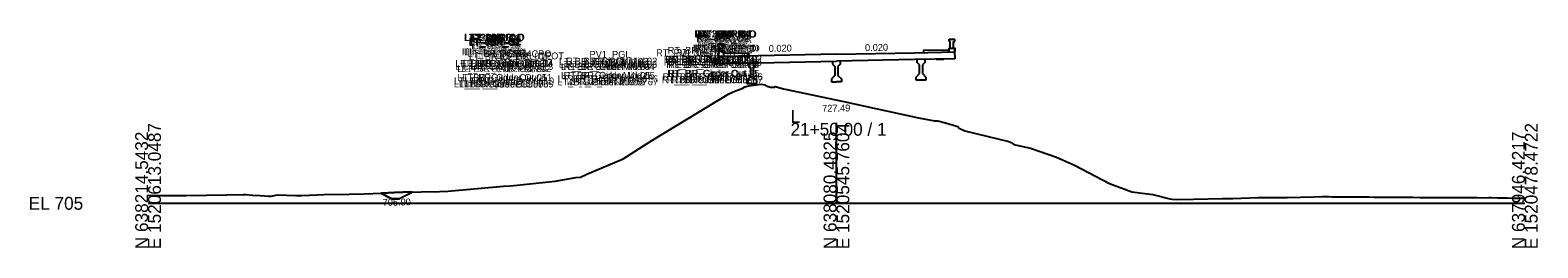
# Model space of a CAD drawing. Extents: x -26 to 3903, y -10 to 9531.
# Drawn here: x 974.3 to 1302.8, y 1490.3 to 1537.7 of the extents above; entities that cross this region are included whole.
import ezdxf

# ---------------------------------------------------------------- set-up
doc = ezdxf.new("R2010")
doc.units = 0
for name, color, linetype in [('Default', 7, 'Continuous'), ('Exist Cross Section Cell', 7, 'Continuous'), ('Exist XS Center Line Elevation Label', 7, 'Continuous'), ('Exist XS Ground Line', 7, 'Continuous'), ('Prop CMT Conc Surface', 7, 'Continuous'), ('Prop XS Conc Monolithic Island', 7, 'Continuous'), ('Prop XS DDE', 7, 'Continuous'), ('Prop XS DDE Earthwork Shape', 7, 'Continuous'), ('Prop XS DDE Elevations', 7, 'Continuous'), ('Prop XS Finish Grade', 7, 'Continuous'), ('Prop XS SE Text', 7, 'Continuous')]:
    doc.layers.add(name, color=color, linetype=linetype)

msp = doc.modelspace()

# ---------------------------------------------------------------- linework, layer by layer
at = {"layer": 'Exist Cross Section Cell'}
for p, q in [((1150, 1500), (1150, 1517.51)), ((1000, 1500), (1150, 1500)), ((1150, 1500), (1300, 1500))]:
    msp.add_line(p, q, dxfattribs=at)
at = {"layer": 'Exist XS Ground Line'}
msp.add_lwpolyline([(1000, 1501.78), (1001.17, 1501.73), (1008.31, 1501.73), (1017.15, 1501.81), (1020.77, 1501.91), (1021.28, 1501.91), (1022.78, 1501.76), (1024.46, 1501.67), (1026.29, 1501.53), (1026.84, 1501.56), (1028.21, 1501.85), (1032.1, 1501.68), (1033.11, 1501.73), (1033.51, 1501.73), (1038.36, 1501.92), (1043.83, 1501.99), (1047.1, 1502.05), (1050.91, 1502.2), (1053.72, 1502.33), (1055.55, 1502.41), (1063.49, 1502.58), (1065.31, 1502.67), (1077.43, 1503.73), (1078.88, 1503.82), (1080.46, 1503.95), (1084.55, 1504.36), (1088.7, 1504.81), (1093.24, 1505.59), (1094.2, 1505.71), (1095.62, 1506.33), (1103.56, 1509.7), (1107.94, 1512.5), (1110.51, 1514.08), (1126.52, 1523.8), (1128.02, 1524.46), (1129.44, 1524.99), (1130.03, 1525.35), (1130.87, 1525.58), (1133.57, 1525.91), (1134.43, 1525.82), (1134.67, 1525.56), (1135.15, 1525.44), (1135.65, 1525.32), (1135.79, 1525.28), (1136.04, 1525.28), (1136.42, 1525.29), (1136.56, 1525.3), (1136.64, 1525.46), (1138.46, 1524.94), (1139.2, 1524.79), (1152.3, 1522.01), (1158.84, 1520.59), (1167.88, 1518.61), (1171.38, 1517.99), (1172.13, 1517.97), (1173.79, 1517.55), (1176.46, 1516.7), (1176.72, 1516.35), (1177.97, 1515.81), (1187.57, 1513.45), (1188.09, 1513.22), (1188.69, 1512.78), (1192.31, 1512.04), (1197.97, 1510.07), (1201.88, 1508.32), (1209.49, 1504.3), (1214.39, 1502.5), (1218.97, 1501.93), (1222.63, 1501), (1223.14, 1500.9), (1224.13, 1500.84), (1227.83, 1500.92), (1234.12, 1501.02), (1236.36, 1501.08), (1241.89, 1501.28), (1242.48, 1501.29), (1242.88, 1501.29), (1248.18, 1501.28), (1254.05, 1501.41), (1255.67, 1501.45), (1256.77, 1501.47), (1257.26, 1501.46), (1258, 1501.43), (1258.31, 1501.43), (1258.65, 1501.42), (1258.75, 1501.42), (1260.37, 1501.41), (1261.61, 1501.4), (1262.1, 1501.4), (1262.84, 1501.39), (1263.95, 1501.39), (1264.13, 1501.4), (1264.27, 1501.39), (1264.36, 1501.39), (1266.02, 1501.38), (1267.19, 1501.36), (1267.72, 1501.36), (1268.43, 1501.35), (1270.01, 1501.34), (1271.62, 1501.33), (1272.8, 1501.32), (1273.2, 1501.32), (1273.99, 1501.31), (1275.6, 1501.3), (1277.21, 1501.29), (1278.39, 1501.29), (1278.78, 1501.29), (1279.57, 1501.28), (1281.2, 1501.27), (1282.82, 1501.27), (1283.99, 1501.26), (1285.13, 1501.26), (1286.78, 1501.25), (1288.1, 1501.24), (1289.59, 1501.23), (1290.67, 1501.22), (1292.19, 1501.23), (1292.77, 1501.23), (1294.06, 1501.2), (1295.08, 1501.19), (1295.65, 1501.18), (1296.23, 1501.16), (1297.4, 1501.14), (1297.98, 1501.13), (1299.26, 1501.1), (1300, 1501.09)], dxfattribs=at)
at = {"layer": 'Prop XS Conc Monolithic Island'}
for p, q in [((1124.22, 1534.19), (1124.22, 1534.69)), ((1124.22, 1534.69), (1125.47, 1534.69)), ((1125.47, 1534.19), (1125.47, 1534.69)), ((1174.53, 1535.22), (1174.53, 1535.72)), ((1174.53, 1535.72), (1175.78, 1535.72)), ((1174.78, 1535.22), (1174.53, 1535.22)), ((1174.78, 1533.72), (1174.78, 1535.22)), ((1175.53, 1533.72), (1175.53, 1535.22)), ((1175.53, 1535.22), (1175.78, 1535.22)), ((1175.78, 1535.22), (1175.78, 1535.72)), ((1124.47, 1534.19), (1124.22, 1534.19)), ((1124.22, 1531.93), (1124.22, 1532.69)), ((1124.22, 1532.69), (1124.47, 1532.69)), ((1124.47, 1532.69), (1124.47, 1534.19)), ((1125.22, 1532.69), (1125.22, 1534.19)), ((1125.22, 1534.19), (1125.47, 1534.19)), ((1125.47, 1532.69), (1125.22, 1532.69)), ((1125.47, 1531.93), (1125.47, 1532.69)), ((1174.53, 1532.96), (1174.53, 1533.72)), ((1174.53, 1533.72), (1174.78, 1533.72)), ((1175.78, 1533.72), (1175.53, 1533.72)), ((1175.78, 1532.96), (1175.78, 1533.72))]:
    msp.add_line(p, q, dxfattribs=at)
for points in [[(1150, 1532.44), (1133, 1532.1), (1124.22, 1531.93)], [(1124.22, 1531.93), (1124.25, 1530.43)], [(1126.29, 1531.97), (1131, 1532.06)], [(1150, 1532.44), (1167, 1532.78), (1175.78, 1532.96)], [(1175.78, 1531.46), (1167, 1531.28), (1150, 1530.94)], [(1167.59, 1530.64), (1167.59, 1531.29)], [(1169.26, 1531.33), (1169.26, 1530.64)], [(1171.75, 1531.38), (1172.58, 1531.39), (1173.42, 1531.41)], [(1175.75, 1532.99), (1175.78, 1531.46)], [(1124.25, 1530.43), (1133, 1530.6), (1150, 1530.94)], [(1128.25, 1530.51), (1127.42, 1530.49), (1126.58, 1530.47)], [(1130.74, 1530.56), (1130.74, 1529.91)], [(1130.74, 1529.91), (1131.24, 1529.41)], [(1131.24, 1529.41), (1131.24, 1527.49)], [(1131.91, 1529.41), (1132.41, 1529.91)], [(1131.91, 1527.49), (1131.91, 1529.41)], [(1132.41, 1529.91), (1132.41, 1530.59)], [(1149.67, 1527.86), (1148.92, 1527.11)], [(1149.17, 1530.93), (1149.17, 1530.28)], [(1149.17, 1530.28), (1149.67, 1529.78)], [(1149.67, 1529.78), (1149.67, 1527.86)], [(1150.83, 1530.28), (1150.33, 1529.78)], [(1150.33, 1529.78), (1150.33, 1527.86)], [(1150.33, 1527.86), (1151.08, 1527.11)], [(1150.83, 1530.96), (1150.83, 1530.28)], [(1167.34, 1527.48), (1168.09, 1528.23)], [(1168.09, 1530.14), (1167.59, 1530.64)], [(1168.09, 1528.23), (1168.09, 1530.14)], [(1169.26, 1530.64), (1168.76, 1530.14)], [(1168.76, 1530.14), (1168.76, 1528.23)], [(1168.76, 1528.23), (1169.51, 1527.48)], [(1131.24, 1527.49), (1130.49, 1526.74)], [(1130.49, 1526.74), (1130.49, 1526.07)], [(1130.49, 1526.07), (1131.58, 1526.07), (1132.66, 1526.07)], [(1132.66, 1526.74), (1131.91, 1527.49)], [(1132.66, 1526.07), (1132.66, 1526.74)], [(1148.92, 1527.11), (1148.92, 1526.44)], [(1148.92, 1526.44), (1150, 1526.44)], [(1151.08, 1526.44), (1150, 1526.44)], [(1151.08, 1527.11), (1151.08, 1526.44)], [(1167.34, 1526.81), (1167.34, 1527.48)], [(1169.51, 1526.81), (1168.42, 1526.81), (1167.34, 1526.81)], [(1169.51, 1527.48), (1169.51, 1526.81)]]:
    msp.add_lwpolyline(points, dxfattribs=at)
at = {"layer": 'Prop XS DDE'}
for p, q in [((1053.09, 1501), (1050.7, 1502.19)), ((1054.65, 1501), (1057.56, 1502.45)), ((1054.65, 1501), (1053.09, 1501))]:
    msp.add_line(p, q, dxfattribs=at)
at = {"layer": 'Prop XS DDE Earthwork Shape'}
for p, q in [((1050.7, 1502.19), (1053.09, 1501)), ((1054.65, 1501), (1057.56, 1502.45)), ((1057.56, 1502.45), (1055.55, 1502.41)), ((1053.09, 1501), (1054.65, 1501))]:
    msp.add_line(p, q, dxfattribs=at)
msp.add_lwpolyline([(1055.55, 1502.41), (1053.72, 1502.33), (1050.91, 1502.2), (1050.7, 1502.19)], dxfattribs=at)
at = {"layer": 'Prop XS Finish Grade'}
for p, q in [((1130.93, 1532.06), (1130.93, 1532.62)), ((1169.07, 1532.82), (1169.07, 1533.32))]:
    msp.add_line(p, q, dxfattribs=at)
for points in [[(1130.93, 1532.06), (1130.93, 1532.62), (1125.43, 1532.67), (1125.43, 1533.02), (1124.22, 1533.02), (1124.22, 1531.93)], [(1169.07, 1532.82), (1169.07, 1533.32), (1174.57, 1533.43), (1174.57, 1533.78), (1175.78, 1533.78), (1175.78, 1532.96)]]:
    msp.add_lwpolyline(points, dxfattribs=at)

# ---------------------------------------------------------------- texts
at = {"layer": 'Default'}
msp.add_text('-', height=0.0001, dxfattribs=at).set_placement((1000, 1500))
at = {"layer": 'Exist Cross Section Cell'}
for s, p in [('L', (1140, 1517.51)), ('21+50.00 / 1', (1140, 1514.71)), ('EL 705', (974, 1498.6))]:
    msp.add_text(s, height=2.8, dxfattribs=at).set_placement(p)
for s, p in [('N 638214.5432', (1000, 1490)), ('E 1520613.0487', (1002.8, 1490)), ('N 638080.4825', (1150, 1490)), ('E 1520545.7604', (1152.8, 1490)), ('N 637946.4217', (1300, 1490)), ('E 1520478.4722', (1302.8, 1490))]:
    msp.add_text(s, height=2.8, rotation=90, dxfattribs=at).set_placement(p)
at = {"layer": 'Exist XS Center Line Elevation Label'}
msp.add_text('727.49', height=1.5, rotation=0.8401, dxfattribs=at).set_placement((1146.9, 1519.92))
at = {"layer": 'Prop CMT Conc Surface'}
for s, p in [('RT_2BMRP_O', (1119.01, 1536.17)), ('RT_3BMRP_O', (1119.15, 1536.17)), ('RT_5BMRP_O', (1119.24, 1536.09)), ('RT_3BR_O1', (1119.74, 1536.11)), ('RT_2BR_O1', (1119.97, 1536.17)), ('RT_1BR_O1', (1120.23, 1536.17)), ('LT_5BMRP_O', (1068.8, 1535.32)), ('LT_3BMRP_O', (1068.89, 1535.41)), ('LT_2BMRP_O', (1069.03, 1535.41)), ('LT_0BR_O2', (1069.86, 1534.41)), ('LT_2BR_O2', (1069.95, 1534.57)), ('LT_6BR_O2', (1069.95, 1534.24)), ('LT_1BR_O2', (1070.04, 1534.57)), ('LT_0BR_O1', (1070.08, 1535.24)), ('LT_7BR_O1', (1070.08, 1534.24)), ('LT_2BR_O1', (1070.16, 1535.41)), ('LT_6BR_O1', (1070.16, 1535.07)), ('LT_3BR_O2', (1070.18, 1534.51)), ('LT_5BR_O2', (1070.18, 1534.3)), ('LT_4BR_O2', (1070.26, 1534.41)), ('LT_1BR_O1', (1070.26, 1535.41)), ('LT_3BR_O1', (1070.39, 1535.34)), ('LT_7BR_O', (1070.4, 1535.07)), ('LT_0BR_O', (1070.4, 1533.25)), ('LT_6BR_O', (1070.4, 1533)), ('LT_5BR_O1', (1070.41, 1532.76)), ('LT_4BR_O1', (1070.48, 1535.24)), ('LT_1BR_O', (1070.58, 1533.5)), ('LT_5BR_O', (1070.72, 1535.13)), ('LT_2BR_O', (1070.73, 1533.74)), ('LT_3BR_O', (1070.82, 1533.75)), ('LT_4BR_O', (1070.82, 1532.75)), ('RT_BR_2CPO', (1118.73, 1533.01)), ('RT_4BMRP_O', (1119.15, 1533.01)), ('RT_1BMRP_O', (1119.19, 1533.01)), ('RT_4BR_O2', (1119.44, 1535.17)), ('RT_3BR_O2', (1119.52, 1535.27)), ('RT_5BR_O2', (1119.52, 1535.07)), ('RT_6BMRP_O', (1119.63, 1533.01)), ('RT_4BR_O1', (1119.66, 1536)), ('RT_5BR_O1', (1119.73, 1533.52)), ('RT_2BR_O2', (1119.75, 1535.34)), ('RT_6BR_O2', (1119.75, 1535)), ('RT_0BR_O2', (1119.84, 1535.17)), ('RT_3BR_O', (1119.96, 1534.51)), ('RT_4BR_O', (1119.96, 1533.51)), ('RT_6BR_O1', (1119.97, 1535.84)), ('RT_1BR_O2', (1120.02, 1535.34)), ('RT_2BR_O', (1120.05, 1534.5)), ('RT_0BR_O1', (1120.05, 1536)), ('RT_7BR_O1', (1120.05, 1535)), ('RT_5BR_O', (1120.06, 1535.9)), ('RT_BR_1CPO', (1120.12, 1533.01)), ('RT_7BR_O', (1120.38, 1535.84)), ('RT_0BR_O', (1120.38, 1534.01)), ('RT_6BR_O', (1120.38, 1533.76)), ('RT_1BR_O', (1120.56, 1534.26)), ('LT_BR_Girder Out 02', (1066.95, 1529.71)), ('LT_BR_Girder Out 01', (1068, 1529.72)), ('LT_6BMRP_O', (1068.41, 1532.25)), ('LT_BR_1CPO', (1068.57, 1532.25)), ('LT_BR_Girder Out 14', (1068.74, 1529.74)), ('LT_4BMRP_O', (1068.89, 1532.25)), ('LT_1BMRP_O', (1069.21, 1532.25)), ('LT_BR_2CPO', (1069.59, 1532.25)), ('LT_BR_3CPO', (1069.59, 1531.91)), ('LT_BR_06', (1069.88, 1529.66)), ('LT_BR_02', (1069.92, 1531.16)), ('LT_BR_4CPO', (1075.09, 1531.8)), ('LT_PV1_OEOT', (1076.57, 1531.34)), ('LT_BR_01', (1076.85, 1531.3)), ('LT_BR_07', (1078.57, 1529.84)), ('LT_BR_Girder Mid 03', (1089.5, 1529.51)), ('LT_BR_Girder Mid 02', (1089.53, 1530.16)), ('RT_BR_Girder Mid 03', (1091.08, 1529.51)), ('RT_BR_Girder Mid 02', (1091.11, 1530.2)), ('PV1_PGL', (1096.2, 1531.68)), ('BR_PGL', (1096.63, 1530.18)), ('RT_PV1_OEOT', (1110.71, 1532.02)), ('RT_BR_Girder Out 14', (1112.38, 1530.62)), ('RT_BR_Girder Out 13', (1112.4, 1529.97)), ('RT_BR_07', (1112.7, 1530.52)), ('RT_BR_Girder Out 12', (1112.93, 1529.47)), ('RT_BR_4CPO', (1113.23, 1532.56)), ('RT_BR_Girder Out 01', (1113.3, 1530.63)), ('RT_BR_Girder Out 04', (1113.37, 1529.47)), ('RT_BR_Girder Out 03', (1113.89, 1529.97)), ('RT_BR_Girder Out 02', (1113.92, 1530.65)), ('RT_BR_01', (1114.99, 1532.06)), ('RT_BR_3CPO', (1118.73, 1532.67)), ('RT_BR_06', (1121.43, 1530.69)), ('RT_BR_02', (1121.48, 1532.19)), ('LT_BR_Girder Out 03', (1066.92, 1529.06)), ('LT_BR_Girder Out 04', (1067.4, 1528.56)), ('LT_BR_Girder Out 05', (1067.41, 1526.64)), ('LT_BR_Girder Out 12', (1068.29, 1528.56)), ('LT_BR_Girder Out 11', (1068.51, 1526.64)), ('LT_BR_Girder Out 13', (1068.77, 1529.06)), ('LT_BR_Girder Mid 06', (1089.24, 1526.35)), ('LT_BR_Girder Mid 04', (1089.98, 1529.01)), ('LT_BR_Girder Mid 05', (1089.99, 1527.1)), ('RT_BR_Girder Mid 04', (1090.56, 1529.01)), ('RT_BR_Girder Mid 05', (1090.57, 1527.1)), ('RT_BR_Girder Mid 06', (1091.31, 1526.35)), ('RT_BR_Girder Out 09', (1111.96, 1526.13)), ('RT_BR_Girder Out 10', (1112.12, 1526.8)), ('RT_BR_Girder Out 08', (1113.04, 1526.13)), ('RT_BR_Girder Out 11', (1113.15, 1527.55)), ('RT_BR_Girder Out 05', (1113.38, 1527.55)), ('RT_BR_Girder Out 07', (1114.1, 1526.13)), ('RT_BR_Girder Out 06', (1114.12, 1526.8)), ('LT_BR_Girder Out 07', (1066.63, 1525.22)), ('LT_BR_Girder Out 06', (1066.65, 1525.89)), ('LT_BR_Girder Out 08', (1067.73, 1525.22)), ('LT_BR_Girder Out 09', (1068.82, 1525.22)), ('LT_BR_Girder Out 10', (1068.98, 1525.89)), ('LT_BR_Girder Mid 07', (1089.21, 1525.68)), ('RT_BR_Girder Mid 07', (1091.29, 1525.68)), ('BR_Girder Mid 08', (1091.77, 1525.68))]:
    msp.add_text(s, height=1.5, dxfattribs=at).set_placement(p)
at = {"layer": 'Prop XS DDE Elevations'}
msp.add_text('705.00', height=1.5, rotation=0.8401, dxfattribs=at).set_placement((1051.13, 1499.46))
at = {"layer": 'Prop XS SE Text'}
for p in [(1135.26, 1532.96), (1156.24, 1533.13)]:
    msp.add_text('0.020', height=1.5, rotation=1.1458, dxfattribs=at).set_placement(p)

doc.saveas('drawing.dxf')
